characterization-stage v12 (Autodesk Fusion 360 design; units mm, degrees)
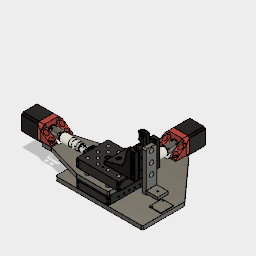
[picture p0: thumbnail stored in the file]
base_feature "Base Feature1"
position "Position1"
sketch "Sketch1" plane through (0, 0, -71.5645) normal (0, 0, -1) x axis (-1, 0, 0)
  circle C1 centre (-38.1, 8.89) radius 4.318
  circle C2 centre (-38.1, 8.89) radius 2
  circle C3 centre (-38.1, 8.89) radius 4.3053
  circle C4 centre (-38.1, 8.89) radius 9.525
  dimension "d1" diameter C4 = 19.05
extrude "Extrude1" sketch "Sketch1" profile of C1 C4 blind 25.4
work_plane "WorkPlane1" AlongDistance 35.56
sketch "Sketch2" plane through (35.56, 0, 0) normal (1, 0, 0) x axis (0, 0, -1)
  line L1 (96.9645, 18.415) -> (96.9645, -0.635)
  line L2 (71.5645, 18.415) -> (71.5645, -0.635)
  line L3 (71.5645, -0.635) -> (96.9645, -0.635)
  line L4 (84.2645, 19.6432) -> (84.2645, -0.635)
  circle C1 centre (74.7395, 15.24) radius 1.27
  circle C2 centre (93.7895, 15.24) radius 1.27
  circle C3 centre (74.7395, 15.24) radius 2.54
  circle C4 centre (93.7895, 15.24) radius 2.54
  point P5 (71.5645, 18.415)
  point P6 (74.7395, 15.24)
  dimension "d5" diameter C1 = 2.54
  dimension "d6" distance P5 P6 = 3.175
  dimension "d7" distance P5 P6 = 3.175
  dimension "d10" diameter C3 = 5.08
extrude "Extrude2" sketch "Sketch2" profile of C1 C2 blind 27.94
extrude "Extrude3" sketch "Sketch2" profile of C1 C2 C3 C4 no distance stored
sketch "Sketch3" plane through (0, 0, -96.9645) normal (0, 0, -1) x axis (-1, 0, 0)
  circle C1 centre (-38.1, 8.89) radius 4.318
  circle C2 centre (-38.1, 8.89) radius 9.525
  circle C3 centre (-38.1, 8.89) radius 4.318
  circle C4 centre (-38.1, 8.89) radius 2.4892
  dimension "d12" diameter C4 = 4.9784
extrude "Extrude4" sketch "Sketch3" profile of C1 C3 C4 blind -6.35
sketch "Sketch4" plane through (0, 0, -96.9645) normal (0, 0, -1) x axis (-1, 0, 0)
  line L1 (-59.055, -12.065) -> (-17.145, -12.065)
  line L2 (-59.055, 29.845) -> (-59.055, -12.065)
  line L3 (-17.145, 29.845) -> (-59.055, 29.845)
  line L4 (-17.145, -12.065) -> (-17.145, 29.845)
  line L5 (-59.055, 29.845) -> (-17.145, -12.065)
  line L6 (-17.145, 29.845) -> (-59.055, -12.065)
  line L7 (-38.1, 29.845) -> (-38.1, 8.89)
  line L8 (-17.145, 8.89) -> (-38.1, 8.89)
  circle C1 centre (-38.1, 8.89) radius 2.4892
  circle C2 centre (-38.1, 8.89) radius 9.525
  circle C3 centre (-38.1, 8.89) radius 2.4892
  circle C4 centre (-38.1, 8.89) radius 11.176
  circle C5 centre (-22.733, 24.257) radius 1.65
  circle C6 centre (-53.467, 24.257) radius 1.65
  circle C7 centre (-22.733, -6.477) radius 1.65
  circle C8 centre (-53.467, -6.477) radius 1.65
  point P6 (-59.055, -12.065)
  point P7 (-59.055, 29.845)
  point P5 (-17.145, -12.065)
  point P10 (-22.733, 24.257)
  point P13 (-53.467, 24.257)
  dimension "d15" diameter C4 = 22.352
  dimension "d16" distance P6 P7 = 41.91
  dimension "d17" distance P5 P6 = 41.91
  dimension "d18" diameter C5 = 3.3
  dimension "d19" distance P10 P13 = 30.734
extrude "Extrude5" new body sketch "Sketch4" profile of C1 C3 along normal blind 22
extrude "Extrude6" sketch "Sketch4" profile of C1 C2 C3 C4 blind 1.7
extrude "Extrude7" sketch "Sketch4" profile of C1 C2 C3 C4 L1 L2 L3 L4 C5 C6 C7 C8 blind 39
chamfer "Chamfer1" distance 3.81
move "Move1"
sketch "Sketch5" plane through (0, -0.762, 0) normal (0, -1, 0) x axis (1, 0, 0)
  line L1 (64.52, 20.4075) -> (11.688, 20.4075)
  line L2 (64.52, 81.3675) -> (64.52, 20.4075)
  line L3 (11.688, 81.3675) -> (64.52, 81.3675)
  line L4 (11.688, 20.4075) -> (11.688, 81.3675)
  line L5 (76.2, 101.6) -> (0, 101.6)
  line L6 (158.75, 101.6) -> (0, 101.6)
  line L7 (158.75, 0) -> (158.75, 101.6)
  line L8 (76.2, 0) -> (158.75, 0)
  line L9 (76.2, -98.4395) -> (76.2, 0)
  line L10 (0, -98.4395) -> (76.2, -98.4395)
  line L11 (0, 101.6) -> (0, -98.4395)
  line L12 (158.75, 0) -> (76.2, 0)
  line L13 (158.75, -98.4395) -> (158.75, 0)
  line L14 (82.8363, -98.4395) -> (158.75, -98.4395)
  line L15 (76.2, 0) -> (76.2, -98.4395)
  line L16 (158.75, 0) -> (70.1363, -98.4395)
  line L17 (38.1, 139.7) -> (38.1, 101.6)
  line L18 (-50.8, 101.6) -> (0, 101.6)
  line L19 (-50.8, 0) -> (-50.8, 101.6)
  line L20 (12.7, -98.4395) -> (-50.8, 0)
  line L21 (0, 0) -> (-50.8, 0)
  circle C1 centre (62.996, 80.0975) radius 1.0922
  circle C2 centre (13.212, 80.0975) radius 1.0922
  circle C3 centre (13.212, 21.6775) radius 1.0922
  circle C4 centre (62.996, 21.6775) radius 1.0922
  circle C5 centre (38.104, 76.2875) radius 1.6002
  circle C6 centre (38.104, 25.4875) radius 1.6002
  circle C7 centre (38.104, 38.1875) radius 3.3655
  circle C8 centre (38.104, 63.5875) radius 3.3655
  circle C9 centre (38.104, 25.4875) radius 1.6002
  circle C10 centre (38.104, 63.5875) radius 3.3655
  circle C11 centre (38.104, 38.1875) radius 3.3655
  circle C12 centre (38.104, 76.2875) radius 1.6002
  circle C13 centre (146.05, -3.1895) radius 3
  circle C14 centre (12.7, -85.7395) radius 3
  circle C15 centre (146.05, 88.9) radius 3
  circle C16 centre (12.7, 88.9) radius 3
  point P30 (158.75, -98.4395)
  point P32 (146.05, -3.1895)
  point P23 (0, -98.4395)
  point P33 (12.7, -85.7395)
  point P18 (158.75, 101.6)
  point P34 (146.05, 88.9)
  point P24 (0, 101.6)
  point P35 (12.7, 88.9)
  point P36 (59.055, -111.1395)
  point P37 (76.2, 101.6)
  point P40 (-50.8, 101.6)
  point P42 (0, 101.6)
  point P44 (12.7, -98.4395)
  point P31 (82.8363, -98.4395)
  point P46 (70.1363, -98.4395)
  dimension "d31" diameter C13 = 6
  dimension "d32" distance P30 P32 = 95.25
  dimension "d33" distance P30 P32 = 12.7
  dimension "d34" diameter C14 = 6 (= "d31")
  dimension "d35" distance P23 P33 = 12.7 (= "d33")
  dimension "d36" distance P23 P33 = 12.7
  dimension "d37" diameter C15 = 6 (= "d31")
  dimension "d38" distance P18 P34 = 12.7 (= "d36")
  dimension "d39" distance P18 P34 = 12.7 (= "d33")
  dimension "d40" diameter C16 = 6 (= "d31")
  dimension "d41" distance P24 P35 = 12.7 (= "d33")
  dimension "d42" distance P24 P35 = 12.7 (= "d36")
  dimension "d45" distance L10 P36 = 12.7
  dimension "d46" distance P18 P37 = 82.55
  dimension "d76" distance P40 P42 = 50.8
  dimension "d77" distance P23 P44 = 12.7
  dimension "d78" distance P31 P46 = 12.7 (= "d35")
extrude "Extrude8" new body sketch "Sketch5" profile of L1 L2 L3 L4 C1 C2 C3 C4 C5 C6 C7 C8 L5 L6 L7 L8 L9 L10 L11 C9 C10 C11 C12 L12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 along normal blind 9.525 bodies "base-plate"
thread "Thread1"
extrude "Extrude9" new body of existing geometry blind 12.7
sketch "Sketch8" plane through (0, 0, -98.4395) normal (0, 0, 1) x axis (1, 0, 0)
  line L1 (20.955, -12.065) -> (17.145, -8.255)
  line L2 (55.245, -12.065) -> (20.955, -12.065)
  line L3 (59.055, -8.255) -> (55.245, -12.065)
  line L4 (59.055, 26.035) -> (59.055, -8.255)
  line L5 (55.245, 29.845) -> (59.055, 26.035)
  line L6 (20.955, 29.845) -> (55.245, 29.845)
  line L7 (17.145, 26.035) -> (20.955, 29.845)
  line L8 (17.145, -8.255) -> (17.145, 26.035)
  circle C1 centre (53.467, -6.477) radius 1.65
  circle C2 centre (53.467, 24.257) radius 1.65
  circle C3 centre (22.733, -6.477) radius 1.65
  circle C4 centre (22.733, 24.257) radius 1.65
  circle C5 centre (38.1, 8.89) radius 11.176
  circle C6 centre (22.733, 24.257) radius 2.8
  circle C7 centre (22.733, -6.477) radius 2.8
  circle C8 centre (53.467, -6.477) radius 2.8
  circle C9 centre (53.467, 24.257) radius 2.8
  dimension "d65" diameter C6 = 5.6
  dimension "d67" C-Pattern1-Angle = 360
extrude "Extrude13" cut sketch "Sketch8" profile of C1 C2 C3 C4 C6 C7 C8 C9 against normal blind 4
sketch "Sketch6" plane through (0, -0.762, 0) normal (0, 1, 0) x axis (-1, 0, 0)
  line L1 (-158.75, 0) -> (-158.75, 101.6)
  line L2 (-12.7, -98.4395) -> (-70.1363, -98.4395)
  line L3 (-158.75, 101.6) -> (50.8, 101.6)
  line L4 (-17.145, -73.0395) -> (-17.145, -98.4395)
  line L5 (-26.797, -73.0395) -> (-17.145, -73.0395)
  line L6 (-26.797, -98.4395) -> (-26.797, -73.0395)
  line L7 (-12.065, -73.0395) -> (-17.145, -73.0395)
  line L8 (-12.065, -98.4395) -> (-12.065, -73.0395)
  line L9 (-12.065, -98.4395) -> (-17.145, -111.1395)
  line L10 (-19.177, -92.0895) -> (-19.177, -79.3895)
  line L11 (-17.145, -98.4395) -> (-12.065, -98.4395)
  line L12 (-17.145, -98.4395) -> (-17.145, -111.1395)
  line L13 (-70.1363, -98.4395) -> (-158.75, 0)
  line L14 (50.8, 0) -> (-12.7, -98.4395)
  line L15 (50.8, 101.6) -> (50.8, 0)
  circle C1 centre (-38.104, 38.1875) radius 2.5175
  circle C2 centre (-38.104, 63.5875) radius 2.5175
  circle C3 centre (-38.104, 76.2875) radius 1.6002
  circle C4 centre (-38.104, 25.4875) radius 1.6002
  circle C5 centre (-19.177, -79.3895) radius 3.1
  circle C6 centre (-19.177, -92.0895) radius 3.1
  circle C7 centre (-19.177, -92.0895) radius 5
  circle C8 centre (-19.177, -79.3895) radius 5
  point P12 (-17.145, -73.0395)
  point P13 (-26.797, -73.0395)
  point P11 (-17.145, -98.4395)
  point P15 (-19.177, -79.3895)
  point P16 (-19.177, -92.0895)
  point P17 (-17.145, -98.4395)
  point P20 (-12.065, -73.0395)
  point P19 (-19.177, -79.3895)
  dimension "d47" distance P12 P13 = 9.652
  dimension "d48" distance P11 P12 = 25.4
  dimension "d51" diameter C5 = 6.2
  dimension "d52" diameter C6 = 6.2 (= "d51")
  dimension "d53" distance P12 P15 = 6.35
  dimension "d54" distance P16 P17 = 6.35
  dimension "d55" diameter C8 = 10
  dimension "d56" diameter C7 = 10 (= "d55")
  dimension "d57" distance P12 P20 = 5.08
  dimension "d58" distance P13 P19 = 7.62
extrude "Extrude10" add sketch "Sketch6" profile of L2 L4 L5 L6 C5 C6 C7 C8 L7 L8 L9 L11 L12 along normal blind 3.175
extrude "Extrude11" add sketch "Sketch6" profile of L2 L4 L5 L6 C7 C8 L7 L8 L9 L11 L12 along normal blind 21.844
sketch "Sketch7" plane through (12.065, 0, 0) normal (-1, 0, 0) x axis (0, 0, 1)
  line L1 (-73.0395, -0.762) -> (-98.4395, -0.762)
  line L2 (-73.0395, 21.082) -> (-73.0395, -0.762)
  line L3 (-98.4395, 21.082) -> (-73.0395, 21.082)
  line L4 (-98.4395, -0.762) -> (-98.4395, 21.082)
  line L5 (-73.0395, 2.413) -> (-98.4395, 21.082)
  point P7 (-73.0395, 2.413)
  point P8 (-73.0395, -0.762)
  dimension "d61" distance P7 P8 = 3.175
extrude "Extrude12" cut sketch "Sketch7" profile of L2 L3 L5 against normal blind 15.24
work_plane "WorkPlane2"
mirror "Mirror1"
chamfer "Chamfer2" distance 4.953
sketch "Sketch9" plane through (17.145, 0, 0) normal (-1, 0, 0) x axis (0, 0, 1)
  line L1 (-111.1395, -8.255) -> (-150.1395, -8.255)
  line L2 (-111.1395, 26.035) -> (-111.1395, -8.255)
  line L3 (-150.1395, 26.035) -> (-111.1395, 26.035)
  line L4 (-150.1395, -8.255) -> (-150.1395, 26.035)
  line L5 (-98.4395, -10.287) -> (-111.1395, -12.065)
  line L6 (-111.1395, -12.065) -> (-111.1395, -8.255)
  line L7 (-98.4395, -12.065) -> (-111.1395, -12.065)
  line L8 (-98.4395, -8.255) -> (-98.4395, -12.065)
  line L9 (-111.1395, -8.255) -> (-98.4395, -8.255)
extrude "Extrude14" cut sketch "Sketch9" profile of L5 L7 L8 no distance stored
copy_paste_bodies "CutPasteBodies1"
base_feature "Base Feature1"
position "Position2"
copy_paste_bodies "CutPasteBodies1"
position "Position3"
sketch "Sketch10" plane through (0, 29.083, 0) normal (0, -1, 0) x axis (1, 0, 0)
  line L1 (-111.5445, 24.896) -> (-111.227, 24.896)
  line L2 (-111.227, 24.769) -> (-111.5445, 24.896)
  line L3 (-85.827, 24.769) -> (-111.227, 24.769)
  line L4 (-85.827, 39.501) -> (-85.827, 24.769)
  line L5 (-111.227, 39.501) -> (-85.827, 39.501)
  line L6 (-111.227, 24.896) -> (-111.227, 39.501)
  line L7 (0, 101.6) -> (-85.827, 76.839)
  line L8 (0, 0) -> (-85.827, 24.769)
  line L9 (76.2, 0) -> (0, 0)
  line L10 (76.2, 101.6) -> (76.2, 0)
  line L11 (0, 101.6) -> (76.2, 101.6)
  line L12 (-111.227, 76.712) -> (-111.227, 67.949)
  line L13 (-111.227, 76.839) -> (-85.827, 76.839)
  line L14 (-111.227, 24.769) -> (-111.227, 76.839)
  line L15 (-111.227, 76.712) -> (-111.5445, 76.712)
  line L16 (-111.227, 62.107) -> (-111.227, 76.712)
  line L17 (-85.827, 62.107) -> (-111.227, 62.107)
  line L18 (-85.827, 76.839) -> (-85.827, 62.107)
  line L19 (-111.227, 76.839) -> (-85.827, 76.839)
  line L20 (-111.5445, 76.712) -> (-111.227, 76.839)
  circle C1 centre (-104.877, 31.881) radius 3.1
  circle C2 centre (-92.177, 31.881) radius 3.1
  circle C3 centre (25.4, 50.8) radius 3.3655
  circle C4 centre (12.7, 50.8) radius 1.6002
  circle C5 centre (50.8, 50.8) radius 3.3655
  circle C6 centre (63.5, 50.8) radius 1.6002
  circle C7 centre (-92.177, 31.881) radius 3.1
  circle C8 centre (-104.877, 31.881) radius 3.1
  circle C9 centre (-92.177, 69.727) radius 3.1
  circle C10 centre (-104.877, 69.727) radius 3.1
  circle C11 centre (-92.177, 69.727) radius 3.1
  circle C12 centre (-104.877, 69.727) radius 3.1
  circle C13 centre (13.1064, 13.3096) radius 3.254
  circle C14 centre (63.0936, 13.3096) radius 3.254
  circle C15 centre (63.0936, 88.2904) radius 3.254
  circle C16 centre (13.1064, 88.2904) radius 3.254
extrude "Extrude15" new body sketch "Sketch10" profile of L3 L4 L5 L6 C1 C2 L7 L8 L9 L10 L11 L12 L13 L14 C3 C4 C5 C6 C7 C8 C9 C10 C11 L16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 along normal blind 9.525 bodies "y-plate"
base_feature "Base Feature1"
position "Position4"
sketch "Sketch11" plane through (107.7863, 0, 0) normal (1, 0, 0) x axis (0, 0, -1)
  line L1 (-57.9922, 109.474) -> (-18.6222, 109.474)
  line L2 (-57.9922, 49.149) -> (-57.9922, 109.474)
  line L3 (-18.6222, 49.149) -> (-57.9922, 49.149)
  line L4 (-18.6222, 109.474) -> (-18.6222, 49.149)
  line L5 (-40.8641, 109.474) -> (-42.9242, 109.474)
  line L6 (-40.8641, 100.33) -> (-40.8641, 109.474)
  line L7 (-35.7841, 100.33) -> (-40.8641, 100.33)
  line L8 (-35.7841, 109.474) -> (-35.7841, 100.33)
  line L9 (-33.6902, 109.474) -> (-35.7841, 109.474)
  line L10 (-33.6902, 117.348) -> (-33.6902, 109.474)
  line L11 (-31.1952, 117.348) -> (-33.6902, 117.348)
  line L12 (-31.1952, 109.474) -> (-31.1952, 117.348)
  line L13 (-18.6222, 109.474) -> (-31.1952, 109.474)
  line L14 (-18.6222, 49.149) -> (-18.6222, 109.474)
  line L15 (-57.9922, 49.149) -> (-18.6222, 49.149)
  line L16 (-57.9922, 109.474) -> (-57.9922, 49.149)
  line L17 (-45.4192, 109.474) -> (-57.9922, 109.474)
  line L18 (-45.4192, 117.348) -> (-45.4192, 109.474)
  line L19 (-42.9242, 117.348) -> (-45.4192, 117.348)
  line L20 (-42.9242, 109.474) -> (-42.9242, 117.348)
  line L21 (-25.6072, 109.474) -> (-51.0072, 109.474)
  line L22 (-25.6072, 17.399) -> (-25.6072, 109.474)
  line L23 (-51.0072, 17.399) -> (-25.6072, 17.399)
  line L24 (-51.0072, 109.474) -> (-51.0072, 17.399)
  line L25 (-38.3072, 109.474) -> (-38.3072, 17.399)
  line L26 (-51.0072, 20.5105) -> (-25.6072, 20.5105)
  line L27 (-51.0072, 26.9875) -> (-51.0072, 20.5105)
  line L28 (-25.6072, 26.9875) -> (-51.0072, 26.9875)
  line L29 (-25.6072, 20.5105) -> (-25.6072, 26.9875)
  line L30 (-51.0072, 26.9875) -> (-25.6072, 20.5105)
  line L31 (-25.6072, 26.9875) -> (-51.0072, 20.5105)
  line L32 (-51.0072, 112.649) -> (-51.0072, 109.474)
  line L33 (-25.6072, 112.649) -> (-51.0072, 112.649)
  line L34 (-25.6072, 109.474) -> (-25.6072, 112.649)
  circle C1 centre (-38.3072, 54.3052) radius 3.2
  circle C2 centre (-25.8104, 66.802) radius 3.2
  circle C3 centre (-50.804, 91.7956) radius 3.2
  circle C4 centre (-38.3072, 104.2924) radius 3.2
  circle C5 centre (-25.8104, 91.7956) radius 3.2
  circle C6 centre (-38.3072, 79.2988) radius 3.2
  circle C7 centre (-50.804, 66.802) radius 3.2
  circle C8 centre (-38.3072, 54.3052) radius 2.5
  circle C9 centre (-25.8104, 66.802) radius 2.5
  circle C10 centre (-50.804, 66.802) radius 2.5
  circle C11 centre (-38.3072, 79.2988) radius 2.5
  circle C12 centre (-25.8104, 91.7956) radius 2.5
  circle C13 centre (-50.804, 91.7956) radius 2.5
  circle C14 centre (-38.3072, 104.2924) radius 3.2
  circle C15 centre (-38.3072, 23.749) radius 2.15
  point P38 (-25.6072, 17.399)
  point P39 (-51.0072, 17.399)
  point P5 (-18.6222, 49.149)
  point P47 (-38.3072, 23.749)
  point P37 (-25.6072, 109.474)
  point P49 (-25.6072, 112.649)
  dimension "d79" distance P38 P39 = 25.4
  dimension "d80" distance P5 P38 = 31.75
  dimension "d81" diameter C15 = 4.3
  dimension "d82" distance L26 L28 = 6.477
  dimension "d83" distance P38 P47 = 6.35
  dimension "d122" distance P37 P49 = 3.175
extrude "Extrude16" new body sketch "Sketch11" profile of L1 L3 C1 C2 C3 C4 C5 C6 C7 L5 L6 L7 L8 L9 L10 L12 L13 L15 L17 L18 L20 C9 C10 C12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 along normal blind 9.525 bodies "z-plate"
extrude "Extrude17" sketch "Sketch11" profile of L22 L24 C15 L26 L27 L28 L29 blind -1.27
sketch "Sketch12" plane through (0, 20.5105, 0) normal (0, 1, 0) x axis (-1, 0, 0)
  line L1 (-117.3113, 25.6072) -> (-117.3113, 51.0072)
  line L2 (-116.0413, 25.6072) -> (-117.3113, 25.6072)
  line L3 (-116.0413, 51.0072) -> (-116.0413, 25.6072)
  line L4 (-117.3113, 51.0072) -> (-116.0413, 51.0072)
  line L5 (-107.7863, 25.6072) -> (-107.7863, 51.0072)
  line L6 (-117.3113, 25.6072) -> (-107.7863, 25.6072)
  line L7 (-117.3113, 51.0072) -> (-117.3113, 25.6072)
  line L8 (-107.7863, 51.0072) -> (-117.3113, 51.0072)
  line L9 (-116.0413, 51.0072) -> (-116.0413, 25.6072)
  line L10 (-144.6163, 51.0072) -> (-116.0413, 51.0072)
  line L11 (-144.6163, 25.6072) -> (-144.6163, 51.0072)
  line L12 (-116.0413, 25.6072) -> (-144.6163, 25.6072)
  line L13 (-116.0413, 51.0072) -> (-116.0413, 25.6072)
  circle C1 centre (-131.9163, 38.3072) radius 2
  point P12 (-116.0413, 51.0072)
  point P13 (-144.6163, 51.0072)
  point P16 (-131.9163, 38.3072)
  dimension "d89" distance P12 P13 = 28.575
  dimension "d90" diameter C1 = 4
  dimension "d91" distance L11 P16 = 12.7
  dimension "d92" distance L10 P16 = 12.7
extrude "Extrude18" sketch "Sketch12" profile of L1 L2 L3 L4 L6 L7 L8 L9 L10 L11 L12 L13 C1 blind 6.35
sketch "Sketch13" plane through (0, -0.762, 0) normal (0, 1, 0) x axis (-1, 0, 0)
  line L1 (-158.75, 101.6) -> (50.8, 101.6)
  line L2 (-158.75, 0) -> (-158.75, 101.6)
  line L3 (-70.1363, -98.4395) -> (-158.75, 0)
  line L4 (-12.7, -98.4395) -> (-70.1363, -98.4395)
  line L5 (50.8, 0) -> (-12.7, -98.4395)
  line L6 (50.8, 101.6) -> (50.8, 0)
  line L7 (-127.0903, 23.0672) -> (-155.0303, 23.0672)
  line L8 (-127.0903, 53.5472) -> (-127.0903, 23.0672)
  line L9 (-155.0303, 53.5472) -> (-127.0903, 53.5472)
  line L10 (-155.0303, 23.0672) -> (-155.0303, 53.5472)
  line L11 (-127.0903, 38.3072) -> (-131.9163, 38.3072)
  line L12 (-26.797, -68.3895) -> (-26.797, -73.0395)
  line L13 (-49.403, -68.3895) -> (-26.797, -68.3895)
  line L14 (-49.403, -73.0395) -> (-49.403, -68.3895)
  line L15 (-49.403, -98.4395) -> (-49.403, -73.0395)
  line L16 (-20.955, -98.4395) -> (-55.245, -98.4395)
  line L17 (-26.797, -73.0395) -> (-26.797, -98.4395)
  line L18 (-26.797, -98.4395) -> (-26.797, -73.0395)
  circle C1 centre (-38.104, 76.2875) radius 1.6002
  circle C2 centre (-38.104, 63.5875) radius 2.5175
  circle C3 centre (-38.104, 25.4875) radius 1.6002
  circle C4 centre (-38.104, 38.1875) radius 2.5175
  circle C5 centre (-131.9163, 38.3072) radius 2
  circle C6 centre (-131.9163, 50.8072) radius 1.35
  circle C7 centre (-131.9163, 25.8072) radius 1.35
  circle C8 centre (-57.023, -92.0895) radius 3.1
  circle C9 centre (-57.023, -79.3895) radius 3.1
  circle C10 centre (-19.177, -79.3895) radius 3.1
  circle C11 centre (-19.177, -92.0895) radius 3.1
  point P13 (-131.9163, 50.8072)
  point P14 (-131.9163, 25.8072)
  point P12 (-131.9163, 38.3072)
  point P15 (-155.0303, 23.0672)
  point P16 (-127.0903, 23.0672)
  point P18 (-155.0303, 53.5472)
  point P28 (-49.403, -68.3895)
  point P39 (-47.625, -71.5645)
  dimension "d95" diameter C6 = 2.7
  dimension "d98" distance P13 P14 = 25
  dimension "d99" distance P12 P15 = 23.114
  dimension "d100" distance P15 P16 = 27.94
  dimension "d101" distance P15 P18 = 30.48
  dimension "d106" distance P28 P39 = 3.175
  dimension "d97" C-Pattern1-Angle = 360
extrude "Extrude19" cut sketch "Sketch13" profile of L4 C6 C7 C8 C9 C10 C11 L12 L13 L14 L15 L16 L17 L18 no distance stored
extrude "Extrude20" new body sketch "Sketch13" profile of L2 C5 C6 C7 L7 L8 L9 L10 L11 along normal blind 1.524
thread "Thread2"
sketch "Sketch14" plane through (0, 29.083, 0) normal (0, 1, 0) x axis (-1, 0, 0)
  line L1 (-76.2, 101.6) -> (0, 101.6)
  line L2 (-76.2, 0) -> (-76.2, 101.6)
  line L3 (0, 0) -> (-76.2, 0)
  line L4 (85.827, 24.769) -> (0, 0)
  line L5 (111.227, 24.769) -> (85.827, 24.769)
  line L6 (111.227, 76.839) -> (111.227, 24.769)
  line L7 (85.827, 76.839) -> (111.227, 76.839)
  line L8 (0, 101.6) -> (85.827, 76.839)
  line L9 (85.827, 62.107) -> (85.827, 76.839)
  line L10 (82.652, 62.107) -> (85.827, 62.107)
  line L11 (82.652, 39.501) -> (82.652, 62.107)
  line L12 (85.827, 39.501) -> (82.652, 39.501)
  line L13 (111.227, 39.501) -> (85.827, 39.501)
  line L14 (111.227, 67.949) -> (111.227, 33.659)
  line L15 (85.827, 62.107) -> (111.227, 62.107)
  circle C1 centre (-13.1064, 88.2904) radius 3.254
  circle C2 centre (104.877, 69.727) radius 2.5175
  circle C3 centre (-25.4, 50.8) radius 2.5175
  circle C4 centre (92.177, 31.881) radius 2.5175
  circle C5 centre (-63.5, 50.8) radius 1.6002
  circle C6 centre (104.877, 31.881) radius 2.5175
  circle C7 centre (-63.0936, 88.2904) radius 3.254
  circle C8 centre (92.177, 69.727) radius 2.5175
  circle C9 centre (-50.8, 50.8) radius 2.5175
  circle C10 centre (-13.1064, 13.3096) radius 3.254
  circle C11 centre (-12.7, 50.8) radius 1.6002
  circle C12 centre (-63.0936, 13.3096) radius 3.254
  circle C13 centre (-63.0936, 88.2904) radius 5.25
  circle C14 centre (-13.1064, 88.2904) radius 5.25
  circle C15 centre (-13.1064, 13.3096) radius 5.25
  circle C16 centre (-63.0936, 13.3096) radius 5.25
  point P35 (82.652, 39.501)
  point P36 (85.827, 39.501)
  dimension "d107" distance P35 P36 = 3.175
  dimension "d111" diameter C13 = 10.5
  dimension "d112" diameter C16 = 10.5 (= "d111")
  dimension "d113" diameter C15 = 10.5 (= "d111")
  dimension "d114" diameter C14 = 10.5 (= "d111")
extrude "Extrude21" sketch "Sketch14" profile of L6 L10 L11 L12 L13 L14 L15 blind -9.525
extrude "Extrude22" sketch "Sketch14" profile of C1 C7 C10 C12 C13 C14 C15 C16 blind -7.62
fillet "Fillet2" radius 3.175
sketch "Sketch15" plane through (117.3113, 0, 0) normal (1, 0, 0) x axis (0, 0, -1)
  line L1 (-51.0072, 26.9875) -> (-51.0072, 109.474)
  line L2 (-25.6072, 26.9875) -> (-51.0072, 26.9875)
  line L3 (-25.6072, 109.474) -> (-25.6072, 26.9875)
  line L4 (-47.8322, 112.649) -> (-28.7822, 112.649)
  circle C1 centre (-38.3072, 79.2988) radius 3.2
  circle C2 centre (-38.3072, 54.3052) radius 3.2
  circle C3 centre (-38.3072, 104.2924) radius 3.2
  circle C4 centre (-38.3072, 104.2924) radius 5.25
  circle C5 centre (-38.3072, 79.2988) radius 5.25
  circle C6 centre (-38.3072, 54.3052) radius 5.25
  arc A1 centre (-47.8322, 109.474) radius 3.175 clockwise from (-51.0072, 109.474) to (-47.8322, 112.649)
  arc A2 centre (-28.7822, 109.474) radius 3.175 clockwise from (-28.7822, 112.649) to (-25.6072, 109.474)
  dimension "d117" diameter C4 = 10.5
  dimension "d118" diameter C5 = 10.5 (= "d117")
  dimension "d119" diameter C6 = 10.5 (= "d117")
extrude "Extrude23" cut sketch "Sketch15" profile of C1 C2 C3 C4 C5 C6 against normal blind 7.62
component_from_bodies "Body->Comp1"
component_from_bodies "Body->Comp2"
component_from_bodies "Body->Comp3"
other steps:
base_feature "Base Feature1" bodies "base-plate"
base_feature "Base Feature1" bodies "y-plate"
base_feature "Base Feature1" bodies "z-plate"
base_feature "Base Feature2"
base_feature "Base Feature2"
create_component "CreateComponent1"
remove_body "RemoveBody1"
remove_body "RemoveBody2"
remove_body "RemoveBody3"
create_component "CreateComponent3"
create_component "CreateComponent4"
create_component "CreateComponent5"
remove_body "RemoveBody4"
create_component "CreateComponent6"
remove_body "RemoveBody5"
create_component "CreateComponent7"
remove_body "RemoveBody6"
named bodies: "base-plate", "y-plate", "z-plate"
